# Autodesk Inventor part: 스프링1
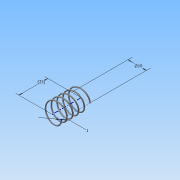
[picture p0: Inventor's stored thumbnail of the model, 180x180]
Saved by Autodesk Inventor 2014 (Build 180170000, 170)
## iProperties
Created: 2015-06
Part Number: 스프링1
Material: 강철, 연강
Document SubType Name: Modeling
Designer: Administrator
Density: 7.86 g/cm^3
Appearance: 강철
Mass: 1.53479 g
Surface Area: 7.89194 cm^2
Volume: 0.195266 cm^3
Author: Administrator
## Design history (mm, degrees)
sketch "스케치1"
  geometry: L1 (0, 0)-(8, 0); L2 (8, 0)-(8, 21.5); L3 (8, 21.5)-(0, 21.5); L4 (0, 21.5)-(0, 0); C1 r 0.5 at (8, 0)
  constraints: 8 end point, 2 parallel, 1 centre point, 1 coincident, 1 horizontal, 1 perpendicular
  dimensions: "d0" = 21.5 distance of L3.end L1.start (derived); "d1" = 16 diameter of L2 L4; "d2" = 1 diameter of C1
feature "코일1" sketch "스케치1" pitch "d3" = 10; turns "d5" = 5; dims "d4" = 21.5 (= d0), "d6" = 0, angle "d7" = 90 deg, angle "d8" = 90 deg, "d9" = 0, "d10" = 0
sketch "스케치2"
  geometry: L1 (-8.5, 0)-(-7.5, 0) reference; 1 further point
  constraints: 1 horizontal alignment
extrude "돌출1" cut sketch "스케치2" stored distance "d11" = 10; taper "d12" = 0 deg
node "작업 평면1"
sketch "스케치3"
  geometry: L1 (-7.5, 0)-(-8.5, 0) reference; 1 further point
  constraints: 1 horizontal alignment
extrude "돌출2" cut sketch "스케치3" stored distance "d14" = 10; taper "d15" = 0 deg
node "솔리드1"
node "절단 모서리 투영1"
node "절단 모서리 투영2"
other parameters: "d13" = 21.5 (= d0)
